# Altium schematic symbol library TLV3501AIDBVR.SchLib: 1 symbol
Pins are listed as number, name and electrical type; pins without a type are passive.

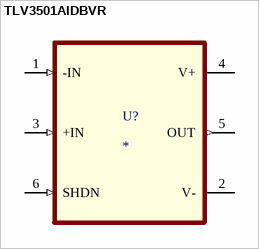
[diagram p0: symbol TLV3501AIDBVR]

## TLV3501AIDBVR
designator U?
4.5ns, Rail-to-Rail, High Speed Comparator with Shutdown 6-SOT-23 -40 to 125; MP: TLV3501AIDBVR
footprint TLV3501AIDBVR
pins: 1 -IN (in), 2 V- (power), 3 +IN (in), 4 V+ (power), 5 OUT (out), 6 SHDN (in)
